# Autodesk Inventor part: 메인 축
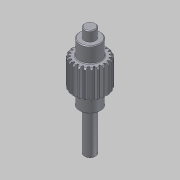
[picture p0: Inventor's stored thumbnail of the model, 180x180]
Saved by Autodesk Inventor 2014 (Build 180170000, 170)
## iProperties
Created: 2013-12
Part Number: 메인 축
Material: 강
Document SubType Name: Modeling
Designer: 한국산업디자인학원
Categories: <?xml version="1.0" encoding="UTF-16"?> <MemberInstance><Categories><FamilyTemplate><FamilyTemplateParameter ValueType="xs:double" Id="1" ObjectReferenceKey="da
Density: 1 g/cm^3
Appearance: 강철
CustomPartVersion: 1
Author: 한국산업디자인학원
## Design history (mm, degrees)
sketch "Sketch1"
  geometry: C1 r 12 at (0, 0)
  constraints: 1 centre point
  dimensions: "d0" = 24 diameter of C1 (= da_da)
extrude "Extrusion1" new body sketch "Sketch1" distance "d1" = 20 (= da_b); taper "d2" = 0 deg
workplane "Work Plane2"
feature "피치 지름" dims "d4" = 10, "d5" = 0
workplane "Work Plane8"
workplane "Work Plane9"
chamfer "모따기1" distance "d49" = 1; stored, may be unused: second distance "d50" = 2, angle "d51" = 45 deg
sketch "스케치3"
  geometry: C1 r 7.5 at (0, 0); 1 further point
  constraints: 1 centre point, 1 coincident
  dimensions: "d52" = 15 diameter of C1
extrude "돌출2" join sketch "스케치3" distance "d53" = 11; taper "d54" = 0 deg
sketch "스케치4"
  geometry: C1 r 4 at (0, 0); 1 further point
  constraints: 1 centre point, 1 coincident
  dimensions: "d55" = 8 diameter of C1
extrude "돌출3" join sketch "스케치4" distance "d56" = 7; taper "d57" = 0 deg
sketch "스케치5"
  geometry: C1 r 7.5 at (0, 0) reference; C2 r 7.5 at (0, 0) reference; 1 further point
extrude "돌출4" join sketch "스케치5" distance "d62" = 11; taper "d63" = 0 deg
sketch "스케치6"
  geometry: C1 r 4 at (0, 0); 1 further point
  constraints: 1 centre point, 1 coincident
  dimensions: "d64" = 8 diameter of C1
extrude "돌출5" join sketch "스케치6" distance "d65" = 30; taper "d66" = 0 deg
chamfer "모따기2" distance "d58" = 0.5; stored, may be unused: second distance "d59" = 2, angle "d60" = 45 deg
fillet "모깎기1" dims "d61" = 0.5
feature "스퍼 기어" dims "da_b" = 20, "da_d" = 22, "da_aw" = 31, "da_da" = 24, "da_df" = 19.5, "da_dw" = 22, angle "da_beta" = 0 deg, "da_lefttooth" = 0, "da_righttooth" = 0
body "Solid1"
sketch "Sketch2"
  geometry: C1 r 12 at (0, 0) reference; C2 r 11 at (0, 0)
  constraints: 1 centre point, 1 coincident
  dimensions: "d3" = 22 diameter of C2 (= da_dw)
body "Srf1"
node "투영된 루프1"
other parameters: "d16" = 31 (= da_aw), "d17" = 0, "d34" = 1.428 (computed from da_z), "d39" = 0, "d41" = 0, "d43" = 31 (= da_aw), "d46" = 31 (= da_aw), "d47" = 0, "d48" = 0
